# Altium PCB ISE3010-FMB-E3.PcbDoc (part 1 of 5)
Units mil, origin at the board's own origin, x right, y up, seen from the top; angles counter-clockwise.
Board outline 7874.02 x 2362.2 mil, 4 copper layers (Top Layer, MidLayer1, MidLayer2, Bottom Layer), stack 55.6 mil thick; 507 components, 331 nets, 1707 pads, 610 vias.
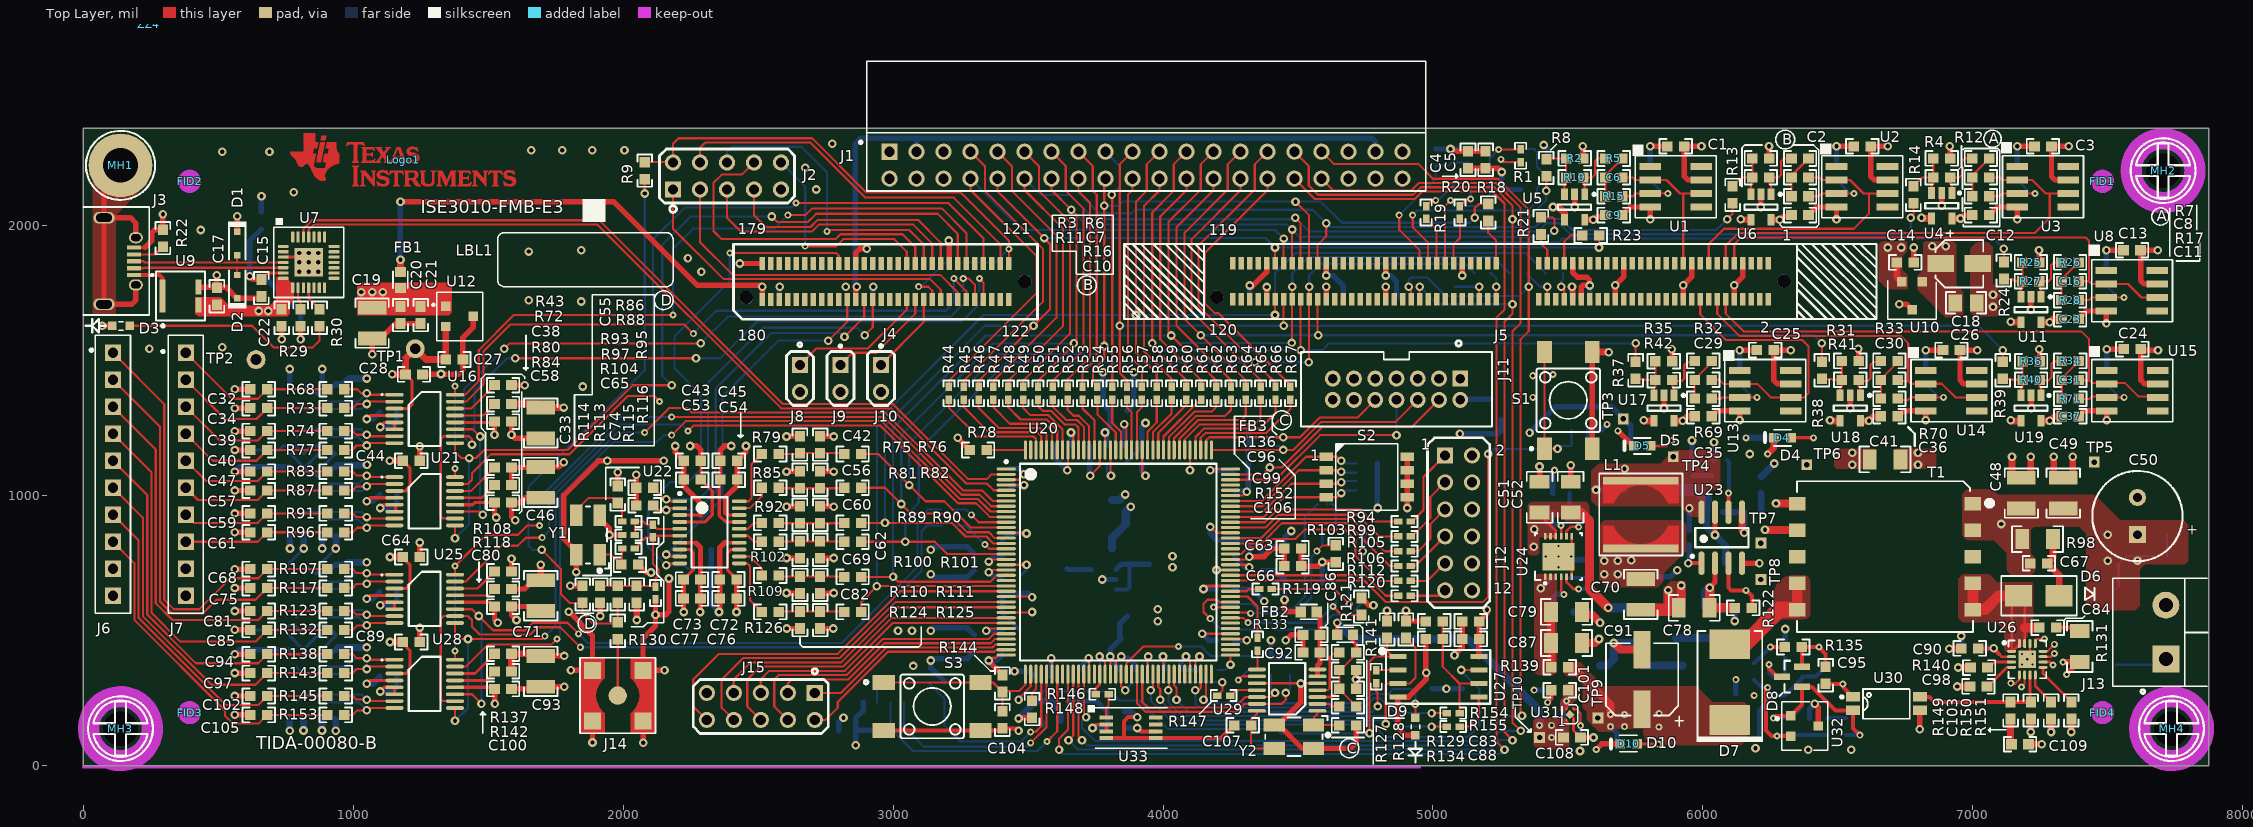
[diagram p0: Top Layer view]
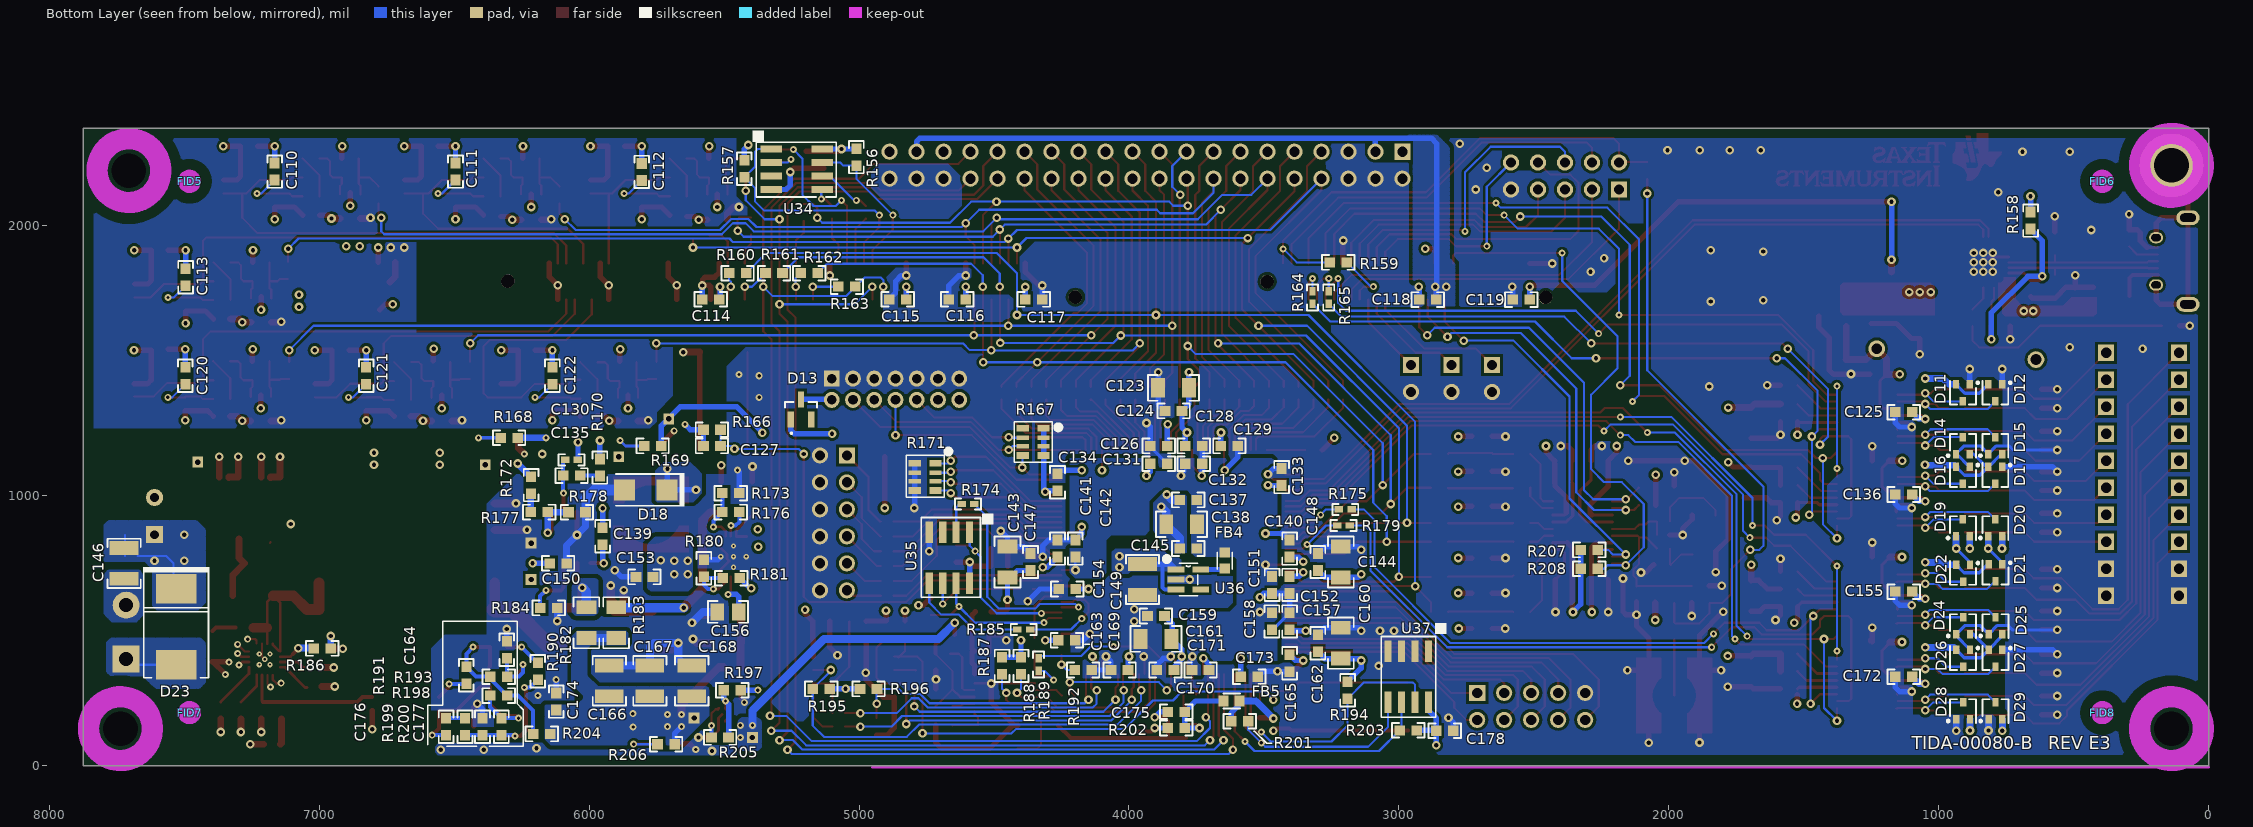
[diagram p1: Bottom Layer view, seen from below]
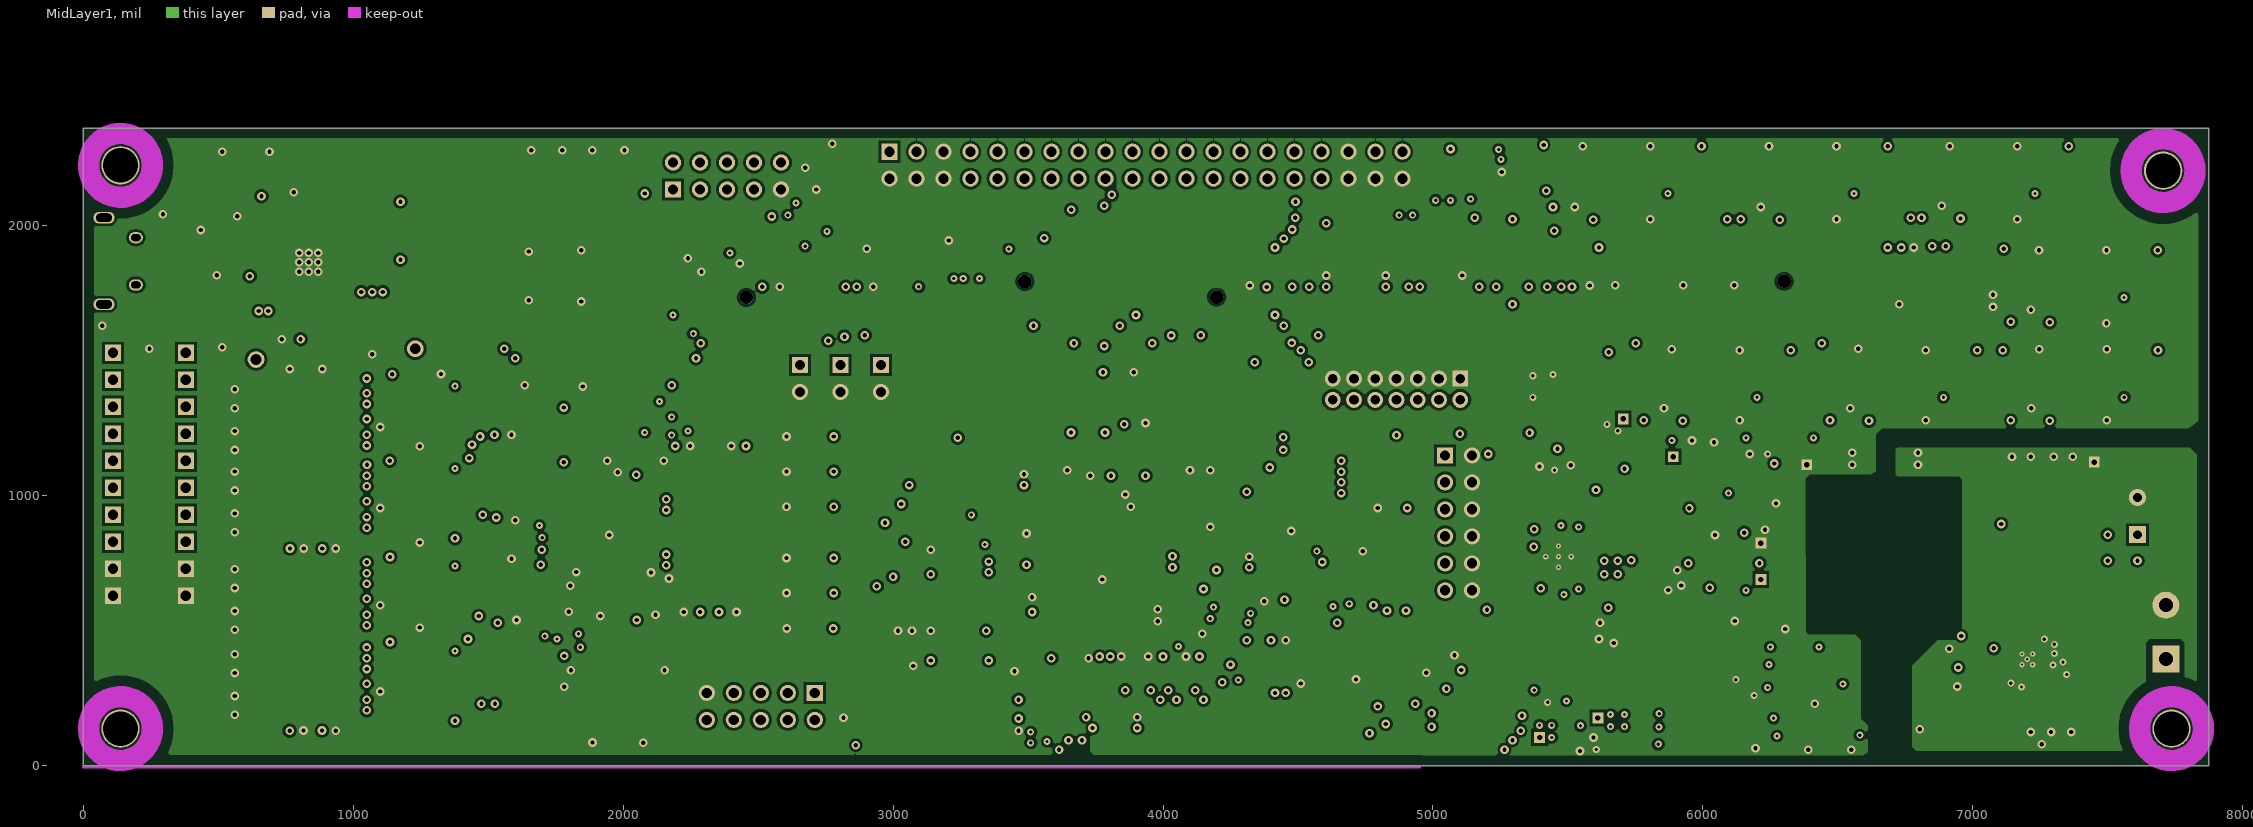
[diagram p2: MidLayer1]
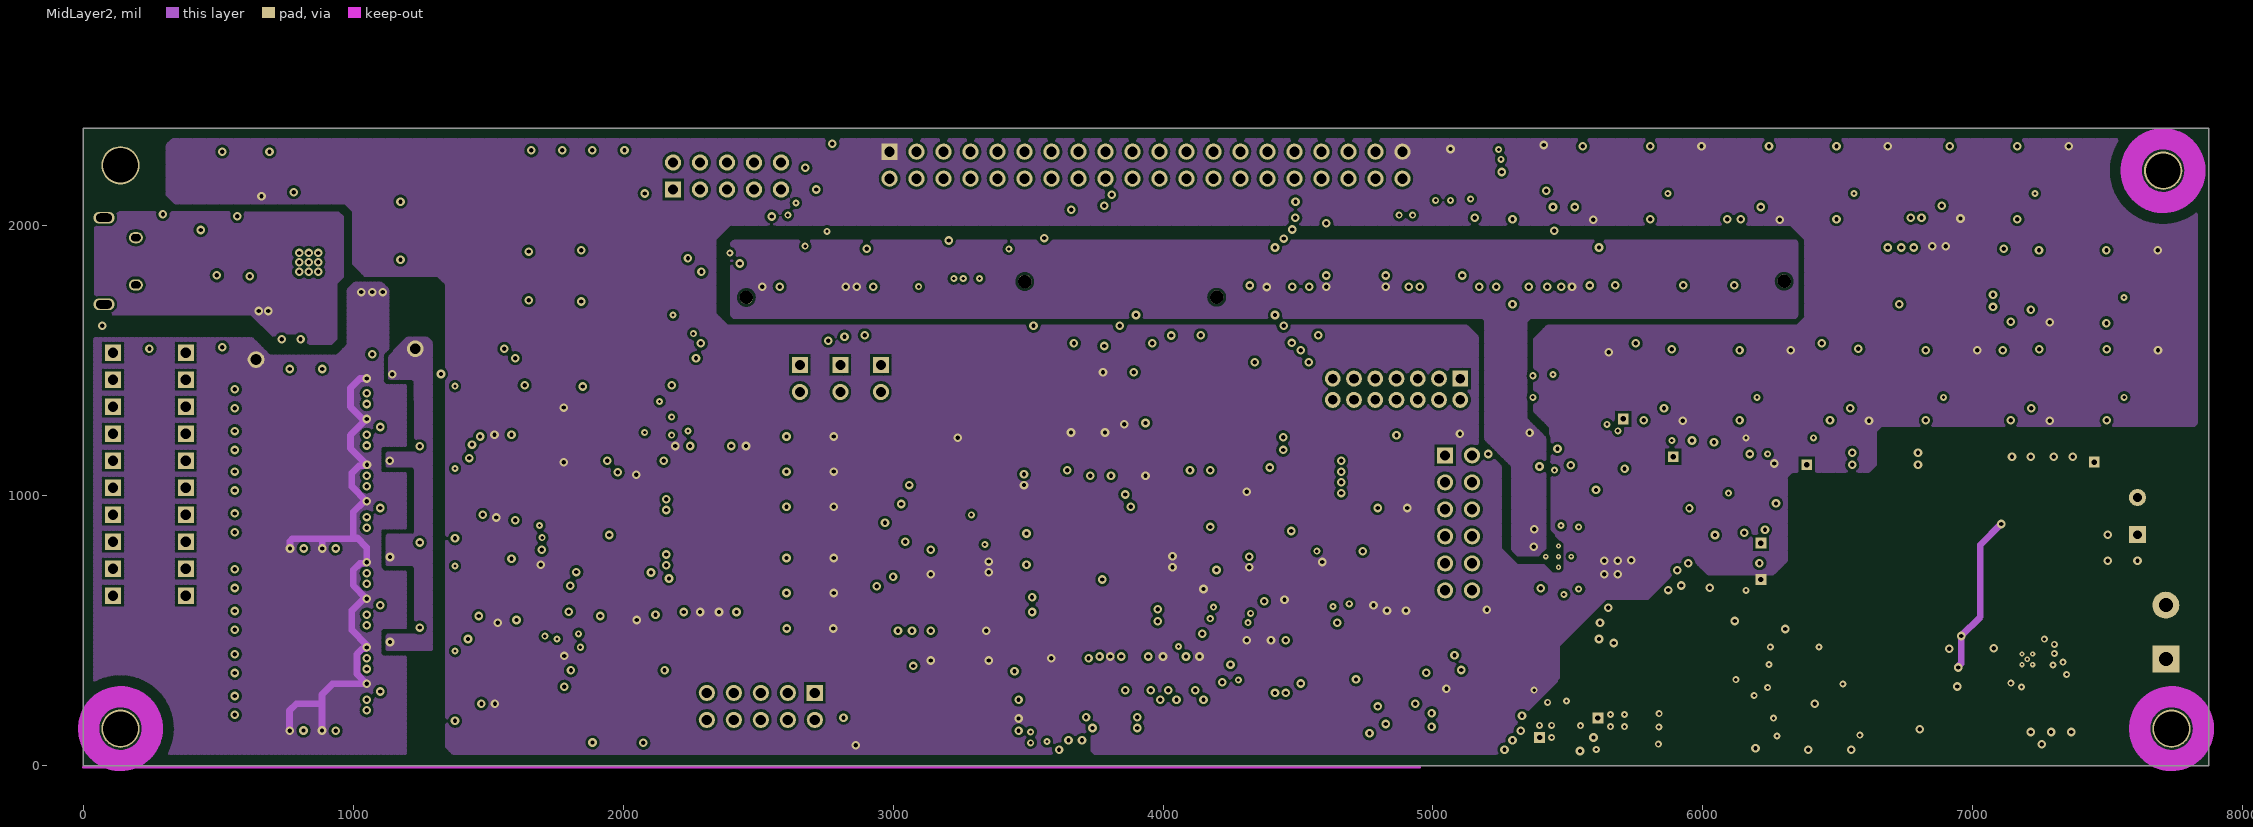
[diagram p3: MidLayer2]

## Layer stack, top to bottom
Top Layer: signal copper 1.4
Dielectric: core 16.6, FR-4, Dk 4.8
MidLayer1: signal copper 1.4
Dielectric: prepreg 16.8, FR-4, Dk 4.8
MidLayer2: signal copper 1.4
Dielectric: core 16.6, FR-4, Dk 4.8
Bottom Layer: signal copper 1.4

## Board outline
0,0 7874.02,0 7874.02,2362.2 0,2362.2

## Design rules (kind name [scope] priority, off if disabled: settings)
AcuteAngle [All] p1 off: minimum=4.50000000000000E+0001 checktracksonly=FALSE
AssemblyTestPointUsage [All] p1 off: valid=2
AssemblyTestpoint [All] p1 off: testpointundercomponent=TRUE minsize=40 maxsize=100 preferedsize=60 minholesize=0 maxholesize=40 preferedholesize=32 testpointgrid=1 usegrid=TRUE gridtolerance=0.01 allowsidetop=TRUE allowsidebottom=TRUE
Clearance "via to via" [IsVia vs IsVia] p1: gap=7.8
Clearance "Via to SMT Pin" [IsVia vs IsSMTPin] p2: gap=7.8
Clearance Clearance_Polygon [InPolygon vs InPolygon] p3: gap=15
Clearance Clearance_BoardEdge_Poly [OnCopper and InPoly vs IsKeepOut] p4: gap=40
Clearance Clearance_Poly [InPolygon] p5: gap=10
Clearance [All] p6: gap=7.5
ComponentClearance ComponentClearance_Logo [InComponentClass('Logo')] p1 off: gap=50 collisioncheckmode=3 verticalgap=10 showdistances=FALSE
ComponentClearance ComponentClearance_ScrewToNut [(HasFootprint('NY PMS 440 0025 PH')) vs (HasFootprint('Keystone_1902C'))] p2 off: gap=5 collisioncheckmode=3 verticalgap=10 showdistances=FALSE
ComponentClearance ComponentClearance_MountingHoles [InComponentClass('Mounting Holes')] p3 off: gap=250 collisioncheckmode=3 verticalgap=100000 showdistances=FALSE
ComponentClearance ComponentClearance_SmallPassives [HasFootprint('0201*') or HasFootprint('0402*') or HasFootprint('0508') or HasFootprint('0603*') or HasFootprint('0612') or HasFootprint('0805*') or HasFootprint('0815*') or HasFootprint('0830*') or HasFootprint('1206*') or HasFootprint('1210*') or HasFootprint('1808*') or HasFootprint('1812*') or HasFootprint('1825*') or HasFootprint('2010*') or HasFootprint('2220*') or HasFootprint('2225*') or HasFootprint('2512*') or HasFootprint('2728*') or HasFootprint('3518*') vs HasFootprint('0201*') or HasFootprint('0402*') or HasFootprint('0508') or HasFootprint('0603*') or HasFootprint('0612') or HasFootprint('0805*') or HasFootprint('0815*') or HasFootprint('0830*') or HasFootprint('1206*') or HasFootprint('1210*') or HasFootprint('1808*') or HasFootprint('1812*') or HasFootprint('1825*') or HasFootprint('2010*') or HasFootprint('2220*') or HasFootprint('2225*') or HasFootprint('2512*') or HasFootprint('2728*') or HasFootprint('3518*')] p4 off: gap=20 collisioncheckmode=3 verticalgap=10 showdistances=FALSE
ComponentClearance ComponentClearance_THtoSMT [IsThruComponent vs IsSMTComponent] p5 off: gap=100 collisioncheckmode=3 verticalgap=30 showdistances=FALSE
ComponentClearance ComponentClearance_THtoTH [IsThruComponent vs IsThruComponent] p6 off: gap=118.11 collisioncheckmode=3 verticalgap=30 showdistances=FALSE
ComponentClearance [All] p7 off: gap=40 collisioncheckmode=3 verticalgap=10 showdistances=FALSE
DiffPairsRouting DiffPair_RS232DiffPairsRouting [InDifferentialPair ('RS232')] p1 off: maxlimit=8 minlimit=8 mostfreqgap=8 maxuncoupledlength=500
DiffPairsRouting [All] p2 off: maxlimit=8 minlimit=8 mostfreqgap=8 maxuncoupledlength=1000
FabricationTestPointUsage TestPointUsage [All] p1 off: valid=2 allowmultiple=FALSE
FabricationTestpoint Testpoint [All] p1 off: side=3 testpointundercomponent=TRUE minsize=40 maxsize=100 preferedsize=60 minholesize=0 maxholesize=40 preferedholesize=32 testpointgrid=1 allowsidetop=TRUE allowsidebottom=TRUE usegrid=TRUE gridtolerance=0.01
FanoutControl Fanout_LCC [IsLCC] p1 off: bgadir=Out bgaviamode=Centered fanoutstyle=Auto fanoutdirection=Alternating viagrid=1 // Fanout_LCC (Default Rule)
FanoutControl Fanout_BGA [IsBGA] p2 off: bgadir=Out bgaviamode=Centered fanoutstyle=Auto fanoutdirection=Alternating viagrid=1 // Fanout_BGA (Default Rule)
FanoutControl Fanout_SOIC [IsSOIC] p3 off: bgadir=Out bgaviamode=Centered fanoutstyle=Auto fanoutdirection=Alternating viagrid=1 // Fanout_SOIC (Default Rule)
FanoutControl Fanout_Default [All] p4 off: bgadir=Out bgaviamode=Centered fanoutstyle=Auto fanoutdirection=Alternating viagrid=1 // Fanout_Default (Default Rule)
FanoutControl Fanout_Small [(CompPinCount < 5)] p5 off: bgadir=Out bgaviamode=Centered fanoutstyle=Auto fanoutdirection=OutThenIn viagrid=1 // Fanout_Small (Default Rule)
Height [All] p1 off: minheight=0 maxheight=1000 prefheight=500
HoleSize [All] p1: absolutevalues=TRUE maxlimit=251 minlimit=8 maxpercent=80.000 minpercent=20.000
MatchedLengths DiffPair_RS232MatchedLengths [InDifferentialPair ('RS232')] p1: tolerance=1000 checknetsindiffpair=TRUE checkdiffpairvsdiffpair=TRUE checkothers=TRUE
MinimumAnnularRing MinimumAnnularRing_ThermalPadVias [IsVia and InAnyComponent] p1 off: minimumring=5.91
MinimumAnnularRing [All] p2 off: minimumring=9
MinimumSolderMaskSliver MinimumSolderMaskSliver_Logo [InComponentClass('Logo') vs InComponentClass('Logo')] p1 off: minsoldermaskwidth=0.7
MinimumSolderMaskSliver [All] p2 off: minsoldermaskwidth=3.94
NetAntennae [All] p1 off: netantennaetolerance=0
PasteMaskExpansion [All] p1 off: expansion=0
PlaneClearance [All] p1: clearance=15
PlaneConnect [All] p1: planeconnectstyle=Direct reliefexpansion=10 reliefentries=4 reliefconductorwidth=10 reliefairgap=10
PolygonConnect [All] p1: connectstyle=Direct reliefconductorwidth=10 reliefentries=4 polygonreliefangle="90 Angle"
RoutingCorners [All] p1 off: cornerstyle=45-Degree minsetback=100 maxsetback=100
RoutingLayers [All] p1 off: top layer_v5=TRUE mid layer 1_v5=TRUE mid layer 2_v5=TRUE bottom layer_v5=TRUE
RoutingPriority [All] p1 off: routingpriority=0
RoutingTopology [All] p1 off: topology=Shortest
RoutingVias ThermalPadVias [IsVia and InAnyComponent] p1 off: holewidth=16 width=32 viastyle="Through Hole" minholewidth=16 minwidth=32 maxholewidth=16 maxwidth=32
RoutingVias [All] p2: holewidth=12 width=26 viastyle="Through Hole" minholewidth=8 minwidth=20 maxholewidth=16 maxwidth=32
SMDToCorner [All] p1 off: distance=30000
SilkToSilkClearance [All] p1 off: silktosilkclearance=0
SilkscreenOverComponentPads [All] p1 off: minsilkscreentomaskgap=0
SolderMaskExpansion [All] p1 off: expansion=1.97
Width DiffPair_RS232Width [InDifferentialPair('RS232')] p1: maxlimit=100 minlimit=8 preferedwidth=8
Width [All] p2: maxlimit=100 minlimit=8 preferedwidth=20 checkconnectedcopper=TRUE
4 further rules are at their usual default settings.

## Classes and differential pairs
component class "FPGA Power": C104 C123 C124 C126 C128 C129 C131 C132 C133 C134 C137 C138 C140 C141 C142 C143 C144 C147 C148 C151 C152 C154 C157 C158 C159 C160 C161 C162 C163 C165 C169 C170 C171 C173 D9 D13 J11 R144 R167 R175 R179 R192 R196 S3
component class DAC: C28 C32 C33 C34 C38 C39 C40 C44 C46 C47 C57 C58 C59 C61 C64 C68 C71 C75 C80 C81 C85 C89 C93 C94 C97 C100 C102 C105 C125 C136 C155 C172 D11 D12 D14 D15 D16 D17 D19 D20 D21 D22 D24 D25 D26 D27 D28 D29 J6 J7 J12 J15 R43 R68 R72 R73 R74 R77 R80 R83 R84 R87 R91 R96 R107 R108 R117 R118 R123 R132 R137 R138 R142 R143 R145 R153 U16 U21 U25 U28
component class "Mounting Holes": MH1 MH2 MH3 MH4
component class Logo: Logo1
component class Hardware: FID1 FID2 FID3 FID4 FID5 FID6 FID7 FID8 LBL1 Logo1 MH1 MH2 MH3 MH4 ZZ1 ZZ2 ZZ3 ZZ4
component class FiducialMark: FID1 FID2 FID3 FID4 FID5 FID6 FID7 FID8
component class AssemblyNote: ZZ1 ZZ2 ZZ3 ZZ4
component class Label: LBL1
component class "FPGA CLOCK_USB": C15 C17 C22 C42 C43 C45 C53 C54 C55 C56 C60 C62 C63 C65 C66 C69 C72 C73 C74 C76 C77 C82 C83 C86 C88 C92 C96 C99 C106 C107 C127 C175 C178 D1 D2 D3 FB2 FB3 FB5 J3 J14 R9 R22 R29 R30 R44 R45 R46 R47 R48 R49 R50 R51 R52 R53 R54 R55 R56 R57 R58 R59 R60 R61 R62 R63 R64 R65 R66 R67 R75 R76 R78 R79 R81 R82 R85 R86 R88 R89 R90 R92 R93 R94 R95 R97 R99 R100 R101 R102 R103 R104 R105 R106 R109 R110 R111 R112 R113 R114 R115 R116 R119 R120 R121 R124 R125 R126 R127 R128 R129 R130 R133 R134 R136 R141 R146 R147 R148 R152 R154 R155 R158 R166 R171 R174 R185 R187 R188 R189 R194 R195 R201 R202 R203 R207 R208 S1 S2 U7 U9 U20 U22 U27 U29 U33 U35 U37 U59 Y1 Y2
component class "SDM OP Filtering": C1 C2 C3 C6 C7 C8 C9 C10 C11 C12 C13 C14 C16 C18 C19 C20 C21 C23 C24 C25 C26 C27 C29 C30 C31 C35 C36 C37 C110 C111 C112 C113 C120 C121 C122 FB1 R2 R3 R4 R5 R6 R7 R8 R10 R11 R12 R13 R14 R15 R16 R17 R24 R25 R26 R27 R28 R31 R32 R33 R34 R35 R36 R37 R38 R39 R40 R41 R42 R69 R70 R71 TP1 TP2 U1 U2 U3 U4 U5 U6 U8 U10 U11 U12 U13 U14 U15 U17 U18 U19
component class "Control card connector": C4 C5 C114 C115 C116 C117 C118 C119 J1 J2 J4 J5 J8 J9 J10 R1 R18 R19 R20 R21 R23 R156 R157 R159 R160 R161 R162 R163 R164 R165 U34
component class "Power Supply": C41 C48 C49 C50 C51 C52 C67 C70 C78 C79 C84 C87 C90 C91 C95 C98 C101 C103 C108 C109 C130 C135 C139 C145 C146 C149 C150 C153 C156 C164 C166 C167 C168 C174 C176 C177 D4 D5 D6 D7 D8 D10 D18 D23 FB4 J13 L1 R98 R122 R131 R135 R139 R140 R149 R150 R151 R168 R169 R170 R172 R173 R176 R177 R178 R180 R181 R182 R183 R184 R186 R190 R191 R193 R197 R198 R199 R200 R204 R205 R206 T1 TP3 TP4 TP5 TP6 TP7 TP8 TP9 TP10 U23 U24 U26 U30 U31 U32 U36

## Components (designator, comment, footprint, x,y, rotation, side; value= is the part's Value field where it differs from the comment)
C1 "" 0603 5900,2295 r0 top (schematic designator C130)
C2 "" 0603 6590,2295 r0 top (schematic designator C144)
C3 "" 0603 7260,2295 r0 top (schematic designator C152)
C4 "0603YC104JAT2A" 0603 5130,2245 r270 top (schematic designator C114)
C5 "C1608X5R1C105K" 0603 5195,2245 r270 top (schematic designator C115)
C6 "" 0603 5670,2180 r0 top (schematic designator C132)
C7 "" 0603 6360,2180 r0 top (schematic designator C147)
C8 "" 0603 7030,2180 r0 top (schematic designator C154)
C9 "" 0603 5670,2040 r180 top (schematic designator C129)
C10 "" 0603 6360,2040 r180 top (schematic designator C143)
C11 "" 0603 7030,2040 r180 top (schematic designator C151)
C12 "EEE-FC1C100R" SM_RADIAL_B 6950,1860 r0 top (schematic designator C141)
C13 "" 0603 7590,1910 r0 top (schematic designator C146)
C14 "06033C104JAT2A" 0603 6750,1865 r0 top (schematic designator C140)
C15 "GRM188R70J224KA88D" 0603 660,1770 r270 top (schematic designator C63)
C16 "" 0603 7360.31,1795 r0 top (schematic designator C148)
C17 "GRM188R70J224KA88D" 0603 495,1740 r90 top (schematic designator C58)
C18 "0805YC474KAT2A" 0805_HV 6975,1715 r0 top (schematic designator C142)
C19 "" 1210 1070,1640 r270 top (schematic designator C136)
C20 "" 0603 1175,1670 r270 top (schematic designator C138)
C21 "" 0603 1250,1670 r90 top (schematic designator C137)
C22 "C0603C475K9PACTU" 0603 735,1660 r270 top (schematic designator C59)
C23 "" 0603 7360.31,1655 r180 top (schematic designator C145)
C24 "" 0603 7591,1543.54 r0 top (schematic designator C150)
C25 "" 0603 6231,1540 r0 top (schematic designator C134)
C26 "" 0603 6921,1540 r0 top (schematic designator C128)
C27 "" 0603 1375,1505 r0 top (schematic designator C139)
C28 "" 0603 1225,1450 r180 top (schematic designator C9)
C29 "" 0603 6001,1430 r0 top (schematic designator C135)
C30 "" 0603 6691,1430 r0 top (schematic designator C131)
C31 "" 0603 7361,1430 r0 top (schematic designator C153)
C32 "" 0603 650,1395 r0 top (schematic designator C7)
C33 "" 1210 1695,1270 r270 top (schematic designator C105)
C34 "" 0603 650,1325 r0 top (schematic designator C8)
C35 "" 0603 6001,1295 r180 top (schematic designator C133)
C36 "" 0603 6691,1295 r180 top (schematic designator C127)
C37 "" 0603 7361,1295 r180 top (schematic designator C149)
C38 "" 0603 1555,1275 r180 top (schematic designator C13)
C39 "" 0603 650,1240 r0 top (schematic designator C11)
C40 "" 0603 650,1170 r0 top (schematic designator C12)
C41 "" 1206 6675,1135 r180 top (schematic designator C111)
C42 "06031C103KAT2A" 0603 2850,1155 r180 top (schematic designator C39)
C43 "06033C104JAT2A" 0603 2256.5,1130 r0 top (schematic designator C47)
C44 "" 0603 1215,1130 r180 top (schematic designator C17)
C45 "06033C104JAT2A" 0603 2391.5,1130 r180 top (schematic designator C51)
C46 "" 1210 1695,1050 r270 top (schematic designator C22)
C47 "" 0603 650,1090 r0 top (schematic designator C15)
C48 "GRM32ER71H106KA12L" 1210 7180,1010 r90 top (schematic designator C109)
C49 "GRM32ER71H106KA12L" 1210 7335,1010 r90 top (schematic designator C108)
C50 "UHE1H101MPD" HE_800x1150 7610,925 r90 top (schematic designator C112)
C51 "GRM31CR71C106KAC7L" 1206 5395,995 r90 top (schematic designator C180)
C52 "GRM31CR71C106KAC7L" 1206 5510,995 r90 top (schematic designator C181)
C53 "06033C104JAT2A" 0603 2256.5,1060 r0 top (schematic designator C46)
C54 "06033C104JAT2A" 0603 2391.5,1060 r180 top (schematic designator C50)
C55 "06035A270JAT2A" 0603 1980,1005 r90 top (schematic designator C183)
C56 "06031C103KAT2A" 0603 2850,1030 r180 top (schematic designator C40)
C57 "" 0603 650,1020 r0 top (schematic designator C16)
C58 "" 0603 1555,975 r180 top (schematic designator C21)
C59 "" 0603 650,935 r0 top (schematic designator C19)
C60 "06031C103KAT2A" 0603 2850,900 r180 top (schematic designator C41)
C61 "" 0603 650,865 r0 top (schematic designator C20)
C62 "06031C103KAT2A" 0603 2850,830 r180 top (schematic designator C42)
C63 "C1608X5R1C105K" 0603 4480,805 r180 top (schematic designator C117)
C64 "" 0603 1215,773.54 r180 top (schematic designator C25)
C65 "06035A270JAT2A" 0603 2025,745 r0 top (schematic designator C182)
C66 "0603YC104JAT2A" 0603 4480,740 r180 top (schematic designator C116)
C67 "C0603C104K5RACTU" 0603 7245,750 r0 top (schematic designator C123)
C68 "" 0603 650,728.54 r0 top (schematic designator C23)
C69 "06031C103KAT2A" 0603 2850,700 r180 top (schematic designator C43)
C70 "C3225X5R1A226M" 1210 5770,635 r270 top (schematic designator C160)
C71 "" 1210 1695,630 r270 top (schematic designator C30)
C72 "06033C104JAT2A" 0603 2390,690 r0 top (schematic designator C52)
C73 "06033C104JAT2A" 0603 2255,690 r180 top (schematic designator C48)
C74 "06031C103KAT2A" 0603 1980,635 r270 top (schematic designator C45)
C75 "" 0603 650,658.54 r0 top (schematic designator C24)
C76 "06033C104JAT2A" 0603 2390,620 r0 top (schematic designator C53)
C77 "06033C104JAT2A" 0603 2255,620 r180 top (schematic designator C49)
C78 "GMK316AB7106KL" 1206 5967.91,585 r180 top (schematic designator C155)
C79 "12063C105KAT2A" 1206 5495,570 r0 top (schematic designator C178)
C80 "" 0603 1555,590 r180 top (schematic designator C29)
C81 "" 0603 650,573.54 r0 top (schematic designator C27)
C82 "06031C103KAT2A" 0603 2850,570 r180 top (schematic designator C44)
C83 "C0603C475K9PACTU" 0603 5140,535 r0 top (schematic designator C56)
C84 "06035A331JAT2A" 0603 7278,512 r0 top (schematic designator C125)
C85 "" 0603 650,503.54 r0 top (schematic designator C28)
C86 "C0603C475K9PACTU" 0603 4550,485 r0 top (schematic designator C57)
C87 "GRM31CR71C106KAC7L" 1206 5495,455 r0 top (schematic designator C175)
C88 "GRM188R70J224KA88D" 0603 5140,470 r0 top (schematic designator C55)
C89 "" 0603 1215,458.54 r180 top (schematic designator C33)
C90 "C0603C104K5RACTU" 0603 6989,435 r180 top (schematic designator C110)
C91 "UUD1C151MCL1GS" SM_RADIAL_6.3BMM 5775,320 r90 top (schematic designator C119)
C92 "GRM188R70J224KA88D" 0603 4550,420 r0 top (schematic designator C62)
C93 "" 1210 1695,350 r270 top (schematic designator C38)
C94 "" 0603 650,413.54 r0 top (schematic designator C31)
C95 "GRM188R71H393KA61D" 0603 6455,335 r270 top (schematic designator C122)
C96 "C0603C475K9PACTU" 0603 4685,355 r180 top (schematic designator C60)
C97 "" 0603 650,343.54 r0 top (schematic designator C32)
C98 "06035C104KAT2A" 0603 7021,294 r180 top (schematic designator C121)
C99 "GRM188R70J224KA88D" 0603 4685,285.32 r180 top (schematic designator C61)
C100 "" 0603 1555,285 r180 top (schematic designator C37)
C101 "GRM188R71A105KA61D" 0603 5470,280 r180 top (schematic designator C165)
C102 "" 0603 650,258.54 r0 top (schematic designator C35)
C103 "C1608C0G1H101J" 0603 7215,205 r270 top (schematic designator C107)
C104 "C0603C475K9PACTU" 0603 3405,170 r90 top (schematic designator C100)
C105 "" 0603 650,188.54 r0 top (schematic designator C36)
C106 "06035A270JAT2A" 0603 4685,150 r0 top (schematic designator C64)
C107 "06035A270JAT2A" 0603 4295,150 r180 top (schematic designator C65)
C108 "GRM188R71A105KA61D" 0603 5515,105 r0 top (schematic designator C166)
C109 "C0603C104K5RACTU" 0603 7175,80 r0 top (schematic designator C126)
C110 "" 0603 7165,2201.5 r270 bottom (schematic designator C187)
C111 "" 0603 6495,2201.5 r270 bottom (schematic designator C190)
C112 "" 0603 5805,2200 r270 bottom (schematic designator C185)
C113 "" 0603 7495,1810 r270 bottom (schematic designator C186)
C114 "" 0603 5549.21,1728.07 r180 bottom (schematic designator C4)
C115 "" 0603 4856.3,1728.07 r180 bottom (schematic designator C1)
C116 "" 0603 4635.83,1728.07 r180 bottom (schematic designator C2)
C117 "" 0603 4352.36,1728.07 r0 bottom (schematic designator C5)
C118 "" 0603 2893.44,1727.07 r180 bottom (schematic designator C3)
C119 "" 0603 2546.98,1727.07 r180 bottom (schematic designator C6)
C120 "" 0603 7496,1445 r270 bottom (schematic designator C191)
C121 "" 0603 6826,1445 r270 bottom (schematic designator C188)
C122 "" 0603 6136,1445 r270 bottom (schematic designator C189)
C123 "GRM31CR60J107ME39L" 1206 3835,1400 r0 bottom (schematic designator C67)
C124 "C0603C475K9PACTU" 0603 3835,1315 r0 bottom (schematic designator C68)
C125 "" 0603 1130,1310 r180 bottom (schematic designator C10)
C126 "GRM188R70J224KA88D" 0603 3890,1185 r180 bottom (schematic designator C70)
C127 "C0603C475K9PACTU" 0603 5545,1185 r180 bottom (schematic designator C54)
C128 "GRM188R70J224KA88D" 0603 3760,1185 r0 bottom (schematic designator C72)
C129 "GRM188R70J224KA88D" 0603 3627.95,1185 r0 bottom (schematic designator C69)
C130 "GRM1555C1E470JA01D" 0402 6065,1133.5 r180 bottom (schematic designator C158)
C131 "GRM188R70J224KA88D" 0603 3890,1119.02 r0 bottom (schematic designator C71)
C132 "GRM188R70J224KA88D" 0603 3760,1119.02 r0 bottom (schematic designator C84)
C133 "GRM188R70J224KA88D" 0603 3434.65,1069.84 r270 bottom (schematic designator C97)
C134 "GRM188R70J224KA88D" 0603 4265,1050 r270 bottom (schematic designator C83)
C135 "GRM1885C1E681JA01D" 0603 6065,1075 r180 bottom (schematic designator C157)
C136 "" 0603 1130,1005 r180 bottom (schematic designator C18)
C137 "C0603C475K9PACTU" 0603 3780,985 r0 bottom (schematic designator C89)
C138 "GRM31CR60J107ME39L" 1206 3805,895 r0 bottom (schematic designator C90)
C139 "0603YC104JAT2A" 0603 5950,850 r270 bottom (schematic designator C159)
C140 "GRM188R70J224KA88D" 0603 3405,805 r270 bottom (schematic designator C98)
C141 "GRM188R70J224KA88D" 0603 4265,805 r270 bottom (schematic designator C76)
C142 "GRM188R70J224KA88D" 0603 4198.82,805 r270 bottom (schematic designator C88)
C143 "GRM31CR60J107ME39L" 1206 4450,755 r90 bottom (schematic designator C79)
C144 "GRM31CR60J107ME39L" 1206 3215,755 r90 bottom (schematic designator C95)
C145 "C0603C475K9PACTU" 0603 3780,805 r0 bottom (schematic designator C102)
C146 "" 1210 7723,750 r270 bottom (schematic designator C120)
C147 "C0603C475K9PACTU" 0603 4365,755 r90 bottom (schematic designator C80)
C148 "C0603C475K9PACTU" 0603 3300,755 r90 bottom (schematic designator C96)
C149 "" 1210 3950,690 r270 bottom (schematic designator C101)
C150 "GRM188R71C153KA01D" 0603 6115,750 r180 bottom (schematic designator C156)
C151 "GRM188R70J224KA88D" 0603 3470,670 r90 bottom (schematic designator C85)
C152 "GRM188R70J224KA88D" 0603 3405,670 r90 bottom (schematic designator C73)
C153 "C0603X104K8RACTU" 0603 5795,700 r0 bottom (schematic designator C192)
C154 "GRM188R70J224KA88D" 0603 4228.35,655 r180 bottom (schematic designator C81)
C155 "" 0603 1130,645 r180 bottom (schematic designator C26)
C156 "08055C103KAT2A" 0805_HV 5485,570 r0 bottom (schematic designator C179)
C157 "GRM188R70J224KA88D" 0603 3405,535 r270 bottom (schematic designator C99)
C158 "GRM188R70J224KA88D" 0603 3470.47,535 r90 bottom (schematic designator C86)
C159 "C0603C475K9PACTU" 0603 3900,555 r0 bottom (schematic designator C92)
C160 "GRM31CR60J107ME39L" 1206 3215,454.2 r90 bottom (schematic designator C78)
C161 "GRM31CR60J107ME39L" 1206 3900,470 r0 bottom (schematic designator C91)
C162 "C0603C475K9PACTU" 0603 3300,454.2 r90 bottom (schematic designator C77)
C163 "GRM188R70J224KA88D" 0603 4230,465 r0 bottom (schematic designator C82)
C164 "C0603C105K4PACTU" 0603 6305,430 r90 bottom (schematic designator C124)
C165 "GRM188R70J224KA88D" 0603 3405,380 r90 bottom (schematic designator C74)
C166 "GRM32ER61A476KE20L" 1210 5925,315 r90 bottom (schematic designator C104)
C167 "GRM32ER61A476KE20L" 1210 5775,315 r90 bottom (schematic designator C118)
C168 "GRM32ER61A476KE20L" 1210 5620,315 r90 bottom (schematic designator C193)
C169 "GRM188R70J224KA88D" 0603 4035,355 r180 bottom (schematic designator C94)
C170 "GRM188R70J224KA88D" 0603 3865,355 r180 bottom (schematic designator C75)
C171 "GRM188R70J224KA88D" 0603 3735,355 r0 bottom (schematic designator C87)
C172 "" 0603 1130,330 r180 bottom (schematic designator C34)
C173 "GRM188R70J224KA88D" 0603 3555,330 r0 bottom (schematic designator C93)
C174 "C0603X104K8RACTU" 0603 6122,238 r90 bottom (schematic designator C103)
C175 "GRM188R70J224KA88D" 0603 3825,200 r180 bottom (schematic designator C66)
C176 "C1608C0G1H101J" 0603 6530,145 r270 bottom (schematic designator C14)
C177 "C0603C104K5RACTU" 0603 6325,145 r270 bottom (schematic designator C106)
C178 "0603YC104JAT2A" 0603 2830,130 r180 bottom (schematic designator C184)
D1 "PESD1LIN,115" sod-323 570,1935 r270 top (schematic designator D18)
D2 "PESD1LIN,115" sod-323 570,1775 r90 top (schematic designator D19)
D3 "" LED0603AA 140,1630 r0 top (schematic designator D17)
D4 "LG L29K-G2J1-24-Z" LED_0603 6295,1215 r180 top (schematic designator D27)
D5 "LG L29K-G2J1-24-Z" LED_0603 5775,1185 r180 top (schematic designator D28)
D6 "D-MURA105T3" 403D 7245,630 r180 top (schematic designator D23)
D7 "MBRS340T3G" SMC 6100,310 r90 top (schematic designator D22)
D8 "BAT54S-7-F" SOT-23#1 6330,330 r180 top (schematic designator D24)
D9 "" LED0603AA 4935,145 r90 top (schematic designator D21)
D10 "LG L29K-G2J1-24-Z" LED_0603 5725,81 r180 top (schematic designator D29)
D11 "" SOT-323 910.71,1381.57 r270 bottom (schematic designator D1)
D12 "" SOT-323 790.71,1381.57 r270 bottom (schematic designator D3)
D13 "BAS16-7-F" SOT-23#1 5215,1320 r90 bottom (schematic designator D20)
D14 "" SOT-323 910.71,1186.57 r90 bottom (schematic designator D4)
D15 "" SOT-323 790.71,1186.57 r90 bottom (schematic designator D2)
D16 "" SOT-323 910.71,1076.57 r270 bottom (schematic designator D5)
D17 "" SOT-323 790.71,1076.57 r270 bottom (schematic designator D6)
D18 "B220A-13-F" SMA 5790,1022 r0 bottom (schematic designator D26)
D19 "" SOT-323 910.71,881.57 r90 bottom (schematic designator D9)
D20 "" SOT-323 790.71,881.57 r90 bottom (schematic designator D7)
D21 "" SOT-323 790,715 r270 bottom (schematic designator D11)
D22 "" SOT-323 910,713.54 r270 bottom (schematic designator D8)
D23 "MBRS4201T3G" SMC 7530,515 r270 bottom (schematic designator D25)
D24 "" SOT-323 910,518.54 r90 bottom (schematic designator D12)
D25 "" SOT-323 790,518.54 r90 bottom (schematic designator D10)
D26 "" SOT-323 910,398.54 r270 bottom (schematic designator D13)
D27 "" SOT-323 790,398.54 r270 bottom (schematic designator D14)
D28 "" SOT-323 910,203.54 r90 bottom (schematic designator D16)
D29 "" SOT-323 790,203.54 r90 bottom (schematic designator D15)
FB1 "" FB0603 1175,1800 r270 top (schematic designator FB4)
FB2 "" FB0603 4540,570 r0 top (schematic designator FB1)
FB3 "" FB0603 4675,485.32 r0 top (schematic designator FB2)
FB4 "" FB0603 3645,760 r90 bottom (schematic designator FB5)
FB5 "" FB0603 3620,240 r0 bottom (schematic designator FB3)
FID1 "" Fiducial10-20 7480.31,2165.35 r0 top locked (schematic designator FID2)
FID2 "" Fiducial10-20 393.7,2165.35 r0 top locked (schematic designator FID1)
FID3 "" Fiducial10-20 393.7,196.85 r90 top locked (schematic designator FID4)
FID4 "" Fiducial10-20 7480.31,196.85 r0 top (schematic designator FID3)
FID5 "" Fiducial10-20 7480.31,2165.35 r180 bottom (schematic designator FID7)
FID6 "" Fiducial10-20 393.7,2165.35 r180 bottom
FID7 "" Fiducial10-20 7480.31,196.85 r180 bottom (schematic designator FID8)
FID8 "" Fiducial10-20 393.7,196.85 r180 bottom (schematic designator FID5)
J1 "613040243121" CONN_613040243121 3937.01,2225 r0 top locked (schematic designator J4)
J2 "HEADER_2X5" HEADER_2X5 2185,2135 r0 top (schematic designator J7)
J3 "CONN_USB_SD-47590-001" USB-SD-47590-001 80,1870 r0 top (schematic designator J13)
J4 "SPD08-060-RB-TR" HSEC8-130-01-L-DV-A 2972.18,1794 r0 top (schematic designator J6)
J5 "SPD08-120-L-RB" HSEC8-160-01-L-DV-A-L 5250,1795 r0 top
J6 "HEADER_1X10" HDR100_1X10 110,1530 r270 top (schematic designator J11)
J7 "HEADER_1X10" HDR100_1X10 380,1530 r270 top (schematic designator J9)
J8 "" HDR100_1X2 2655,1485 r270 top (schematic designator J3)
J9 "" HDR100_1X2 2805,1485 r270 top (schematic designator J2)
J10 "" HDR100_1X2 2955,1485 r270 top (schematic designator J1)
J11 "0878311420" CONN_0878311420 4865,1395 r180 top (schematic designator J14)
J12 "HEADER_2X6" HEADER_2X6 5045,1150 r270 top (schematic designator J10)
J13 "TBLK_15A_2X5.1MM" TB_2X5.1MM 7715,395 r90 top (schematic designator J15)
J14 "142-0711-201" 142-0711-201 1980,260 r180 top (schematic designator J12)
J15 "HEADER_2X5" HEADER_2X5 2710,270 r180 top (schematic designator J8)
L1 "MSS7341-332NLB" MSS7341 5770,930.49 r270 top (schematic designator L4)
LBL1 "" Label_650x200 1860,1875 r0 top
Logo1 "" TI_Stacked_SolderMask_Small 1185,2245 r0 top
MH1 "" MH3.2 137.8,2224.41 r0 top
MH2 "" MH3.2_NPTH 7705,2205 r0 top (schematic designator MH3)
MH3 "" MH3.2_NPTH 137.8,137.8 r0 top locked (schematic designator MH4)
MH4 "" MH3.2_NPTH 7736.22,137.8 r0 top locked (schematic designator MH2)
R1 "CRCW040222R0JNED" 0402 5325,2260 r90 top (schematic designator R203)
R2 "RC0603FR-07270KL" 0603 5525,2250 r0 top (schematic designator R146)
R3 "RC0603FR-07270KL" 0603 6215,2250 r0 top (schematic designator R160)
R4 "RC0603FR-07270KL" 0603 6885,2250 r0 top (schematic designator R171)
R5 "" 0603 5670,2250 r180 top (schematic designator R141)
R6 "" 0603 6360,2250 r180 top (schematic designator R154)
R7 "" 0603 7030,2250 r180 top (schematic designator R166)
R8 "CRCW06037K50FKEA" 0603 5420,2215 r270 top (schematic designator R144)
R9 "CRCW06030000Z0EA" 0603 2080,2205 r90 top (schematic designator R75)
R10 "CRCW0603100KFKEA" 0603 5525,2180 r0 top (schematic designator R148)
R11 "CRCW0603100KFKEA" 0603 6215,2180 r0 top (schematic designator R162)
R12 "CRCW0603100KFKEA" 0603 6885,2180 r0 top (schematic designator R173)
R13 "CRCW06037K50FKEA" 0603 6110,2115 r270 top (schematic designator R158)
R14 "CRCW06037K50FKEA" 0603 6780,2115 r270 top (schematic designator R169)
R15 "" 0603 5670,2110 r180 top (schematic designator R142)
R16 "" 0603 6360,2110 r180 top (schematic designator R155)
R17 "" 0603 7030,2110 r180 top (schematic designator R167)
R18 "" 0603 5205,2050 r270 top (schematic designator R6)
R19 "CRCW040222R0JNED" 0402 4975,2050 r90 top (schematic designator R204)
R20 "CRCW040222R0JNED" 0402 5100,2050 r90 top (schematic designator R202)
R21 "" 0603 5400,2000 r270 top (schematic designator R4)
R22 "CRCW06030000Z0EA" 0603 295,1955 r270 top (schematic designator R109)
R23 "" 0603 5585,1965 r180 top (schematic designator R2)
R24 "CRCW06037K50FKEA" 0603 7115,1835 r90 top (schematic designator R159)
R25 "RC0603FR-07270KL" 0603 7215.31,1865 r0 top (schematic designator R161)
R26 "" 0603 7360.31,1865 r180 top (schematic designator R156)
R27 "CRCW0603100KFKEA" 0603 7215.31,1795 r0 top (schematic designator R163)
R28 "" 0603 7360.31,1725 r180 top (schematic designator R157)
R29 "CRCW06034K87FKEA" 0603 805,1660 r270 top (schematic designator R103)
R30 "CRCW0603300RJNEA" 0603 875,1660 r270 top (schematic designator R102)
R31 "RC0603FR-07270KL" 0603 6546,1500 r0 top (schematic designator R145)
R32 "" 0603 6001,1500 r180 top (schematic designator R149)
R33 "" 0603 6691,1500 r180 top (schematic designator R139)
R34 "" 0603 7361,1500 r180 top (schematic designator R164)
R35 "RC0603FR-07270KL" 0603 5855.13,1498.7 r0 top (schematic designator R152)
R36 "RC0603FR-07270KL" 0603 7216,1498.54 r0 top (schematic designator R170)
R37 "CRCW06037K50FKEA" 0603 5751,1465 r90 top (schematic designator R151)
R38 "CRCW06037K50FKEA" 0603 6441,1465 r90 top (schematic designator R143)
R39 "CRCW06037K50FKEA" 0603 7111,1465 r90 top (schematic designator R168)
R40 "CRCW0603100KFKEA" 0603 7216,1430 r0 top (schematic designator R172)
R41 "CRCW0603100KFKEA" 0603 6546,1430 r0 top (schematic designator R147)
R42 "CRCW0603100KFKEA" 0603 5855.13,1428.7 r0 top (schematic designator R153)
R43 "CRCW06030000Z0EA" 0603 1555,1410 r0 top (schematic designator R11)
R44 "CRCW040222R0JNED" 0402 3206.81,1380 r270 top (schematic designator R33)
R45 "CRCW040222R0JNED" 0402 3261.81,1380 r270 top (schematic designator R34)
R46 "CRCW040222R0JNED" 0402 3316.81,1380 r270 top (schematic designator R38)
R47 "CRCW040222R0JNED" 0402 3371.81,1380 r270 top (schematic designator R39)
R48 "CRCW040222R0JNED" 0402 3426.81,1380 r270 top (schematic designator R40)
R49 "CRCW040222R0JNED" 0402 3481.81,1380 r270 top (schematic designator R44)
R50 "CRCW040222R0JNED" 0402 3536.81,1380 r270 top (schematic designator R45)
R51 "CRCW040222R0JNED" 0402 3591.81,1380 r270 top (schematic designator R47)
R52 "CRCW040222R0JNED" 0402 3646.81,1380 r270 top (schematic designator R48)
R53 "CRCW040222R0JNED" 0402 3701.81,1380 r270 top (schematic designator R50)
R54 "CRCW040222R0JNED" 0402 3756.81,1380 r270 top (schematic designator R51)
R55 "CRCW040222R0JNED" 0402 3811.81,1380 r270 top (schematic designator R52)
R56 "CRCW040222R0JNED" 0402 3866.81,1380 r270 top
R57 "CRCW040222R0JNED" 0402 3921.81,1380 r270 top (schematic designator R58)
R58 "CRCW040222R0JNED" 0402 3976.81,1380 r270 top (schematic designator R59)
R59 "CRCW040222R0JNED" 0402 4031.81,1380 r270 top (schematic designator R60)
R60 "CRCW040222R0JNED" 0402 4086.81,1380 r270 top (schematic designator R61)
R61 "CRCW040222R0JNED" 0402 4141.81,1380 r270 top (schematic designator R65)
R62 "CRCW040222R0JNED" 0402 4196.81,1380 r270 top (schematic designator R66)
R63 "CRCW040222R0JNED" 0402 4251.81,1380 r270 top (schematic designator R67)
R64 "CRCW040222R0JNED" 0402 4306.81,1380 r270 top (schematic designator R69)
R65 "CRCW040222R0JNED" 0402 4361.81,1380 r270 top (schematic designator R70)
R66 "CRCW040222R0JNED" 0402 4416.81,1380 r270 top (schematic designator R72)
R67 "CRCW040222R0JNED" 0402 4471.81,1380 r270 top (schematic designator R73)
R68 "" 0603 935,1395 r0 top (schematic designator R8)
R69 "" 0603 6001,1360 r180 top (schematic designator R150)
R70 "" 0603 6691,1360 r180 top (schematic designator R140)
R71 "" 0603 7361,1360 r180 top (schematic designator R165)
R72 "CRCW060310K0FKEA" 0603 1555,1340 r0 top (schematic designator R10)
R73 "" 0603 935,1325 r0 top (schematic designator R9)
R74 "" 0603 935,1240 r0 top (schematic designator R12)
R75 "CRCW0603100RJNEA" 0603 2655,1190 r270 top (schematic designator R53)
R76 "CRCW0603100RJNEA" 0603 2730,1190 r90 top (schematic designator R35)
R77 "" 0603 935,1170 r0 top (schematic designator R13)
R78 "CRCW06034K87FKEA" 0603 3315,1170 r180 top (schematic designator R32)
R79 "CRCW06030000Z0EA" 0603 2545,1155 r0 top (schematic designator R41)
R80 "CRCW060310K0FKEA" 0603 1555,1105 r0 top (schematic designator R16)
R81 "CRCW0603100RJNEA" 0603 2655,1060 r270 top (schematic designator R54)
R82 "CRCW0603100RJNEA" 0603 2730,1060 r90 top (schematic designator R36)
R83 "" 0603 935,1090 r0 top (schematic designator R14)
R84 "CRCW060310K0FKEA" 0603 1555,1040 r0 top (schematic designator R15)
R85 "CRCW06030000Z0EA" 0603 2545,1030 r0 top (schematic designator R46)
R86 "RC0603FR-074K7L" 0603 2080,1030 r180 top (schematic designator R42)
R87 "" 0603 935,1020 r0 top (schematic designator R17)
R88 "RC0603FR-074K7L" 0603 2080,965 r180 top (schematic designator R43)
R89 "CRCW0603100RJNEA" 0603 2655,930 r270 top (schematic designator R55)
R90 "CRCW0603100RJNEA" 0603 2730,930 r90 top (schematic designator R37)
R91 "" 0603 935,935 r0 top (schematic designator R18)
R92 "CRCW06030000Z0EA" 0603 2545,900 r0 top (schematic designator R49)
R93 "CRCW04020000Z0ED" 0402 2020,905 r0 top (schematic designator R195)
R94 "CRCW040222R0JNED" 0402 4895,905 r180 top (schematic designator R85)
R95 "CRCW04020000Z0ED" 0402 2110,870 r90 top (schematic designator R78)
R96 "" 0603 935,865 r0 top (schematic designator R19)
R97 "CRCW04020000Z0ED" 0402 2020,855 r0 top (schematic designator R83)
R98 "CRCW12061K50JNEA" 1206 7240,840 r180 top (schematic designator R120)
R99 "CRCW040222R0JNED" 0402 4895,850 r180 top (schematic designator R86)
R100 "CRCW0603100RJNEA" 0603 2655,800 r270 top (schematic designator R62)
R101 "CRCW0603100RJNEA" 0603 2730,800 r90 top (schematic designator R79)
R102 "CRCW06030000Z0EA" 0603 2545,830 r0 top (schematic designator R68)
R103 "CRCW060310K0JNEA" 0603 4640,785 r270 top (schematic designator R213)
R104 "CRCW04020000Z0ED" 0402 2020,805 r0 top (schematic designator R194)
R105 "CRCW040222R0JNED" 0402 4895,795 r180 top (schematic designator R88)
R106 "CRCW040222R0JNED" 0402 4895,740 r180 top (schematic designator R89)
R107 "" 0603 935,728.54 r0 top (schematic designator R20)
R108 "CRCW06030000Z0EA" 0603 1555,720 r0 top (schematic designator R23)
R109 "CRCW06030000Z0EA" 0603 2545,705 r0 top (schematic designator R71)
R110 "CRCW0603100RJNEA" 0603 2655,670 r270 top (schematic designator R63)
R111 "CRCW0603100RJNEA" 0603 2730,670 r90 top (schematic designator R80)
R112 "CRCW040222R0JNED" 0402 4895,685 r180 top (schematic designator R90)
R113 "CRCW0603100RJNEA" 0603 1915,635 r90 top (schematic designator R84)
R114 "CRCW0603100RJNEA" 0603 1850,635 r270 top (schematic designator R82)
R115 "CRCW0603100RJNEA" 0603 2050,635 r270 top (schematic designator R76)
R116 "CRCW04020000Z0ED" 0402 2120,640 r90 top (schematic designator R57)
R117 "" 0603 935,658.54 r0 top (schematic designator R21)
R118 "CRCW060310K0FKEA" 0603 1555,655 r0 top (schematic designator R22)
R119 "CRCW040222R0JNED" 0402 4380,655 r180 top (schematic designator R132)
R120 "CRCW040222R0JNED" 0402 4895,630 r180 top (schematic designator R91)
R121 "CRCW060310K0JNEA" 0603 4735,590 r90 top (schematic designator R214)
R122 "RC0603FR-07150KL" 0603 6150,585 r180 top (schematic designator R176)
R123 "" 0603 935,573.54 r0 top (schematic designator R24)
R124 "CRCW0603100RJNEA" 0603 2655,540 r270 top (schematic designator R64)
R125 "CRCW0603100RJNEA" 0603 2730,540 r90 top (schematic designator R81)
R126 "CRCW06030000Z0EA" 0603 2545,570 r0 top (schematic designator R74)
R127 "CRCW06034K87FKEA" 0603 4830,505 r270 top (schematic designator R92)
R128 "CRCW0603100KFKEA" 0603 4900,505 r270 top (schematic designator R94)
R129 "CRCW0603100RJNEA" 0603 5005,535 r180 top (schematic designator R95)
R130 "CRCW06030000Z0EA" 0603 1980,500 r90 top (schematic designator R77)
R131 "CRCW12066R80JNEA" 1206 7396,442 r90 top (schematic designator R125)
R132 "" 0603 935,503.54 r0 top (schematic designator R25)
R133 "CRCW040222R0JNED" 0402 4350,450 r90 top (schematic designator R108)
R134 "CRCW0603100RJNEA" 0603 5005,470 r0 top (schematic designator R104)
R135 "CRCW060349R9FKEA" 0603 6335,440 r180 top (schematic designator R123)
R136 "CRCW06034K87FKEA" 0603 4685,420 r0 top (schematic designator R106)
R137 "CRCW060310K0FKEA" 0603 1555,415 r0 top (schematic designator R28)
R138 "" 0603 935,413.54 r0 top (schematic designator R26)
R139 "CRCW06030000Z0EA" 0603 5470,365 r0 top (schematic designator R128)
R140 "CRCW06030000Z0EA" 0603 7023,364 r180 top (schematic designator R205)
R141 "CRCW040222R0JNED" 0402 4790,330 r270 top (schematic designator R97)
R142 "CRCW060310K0FKEA" 0603 1555,350 r0 top (schematic designator R27)
R143 "" 0603 935,343.54 r0 top (schematic designator R29)
R144 "CRCW06034K87FKEA" 0603 3405,305 r90 top (schematic designator R116)
R145 "" 0603 935,258.54 r0 top (schematic designator R30)
R146 "CRCW040222R0JNED" 0402 3775,265 r0 top (schematic designator R112)
R147 "CRCW040222R0JNED" 0402 4225,260 r180 top (schematic designator R107)
R148 "CRCW06034K87FKEA" 0603 3515,210 r270 top (schematic designator R111)
R149 "RC0603FR-071K47L" 0603 7140,205 r90 top (schematic designator R189)
R150 "CRCW06030000Z0EA" 0603 7290,205 r270 top (schematic designator R137)
R151 "CRCW0603137KFKEA" 0603 7365,205 r270 top (schematic designator R129)
R152 "CRCW06034K87FKEA" 0603 4685,220.32 r0 top (schematic designator R110)
R153 "" 0603 935,188.54 r0 top (schematic designator R31)
R154 "CRCW040222R0JNED" 0402 5075,195 r0 top (schematic designator R101)
R155 "CRCW040222R0JNED" 0402 5075,145 r180 top (schematic designator R105)
R156 "CRCW060310K0JNEA" 0603 5010,2255 r90 bottom (schematic designator R209)
R157 "CRCW060310K0JNEA" 0603 5425,2211.62 r90 bottom (schematic designator R208)
R158 "CRCW06030000Z0EA" 0603 660,2020 r90 bottom (schematic designator R96)
R159 "CRCW06030000Z0EA" 0603 3225,1865 r180 bottom (schematic designator R131)
R160 "" 0603 5450,1825 r180 bottom (schematic designator R3)
R161 "" 0603 5315,1825 r180 bottom (schematic designator R5)
R162 "" 0603 5185,1825 r180 bottom (schematic designator R7)
R163 "" 0603 5045,1775 r180 bottom (schematic designator R1)
R164 "CRCW040222R0JNED" 0402 3320,1735 r90 bottom (schematic designator R197)
R165 "CRCW040222R0JNED" 0402 3260,1735 r90 bottom (schematic designator R135)
R166 "CRCW06034K87FKEA" 0603 5545,1245 r0 bottom (schematic designator R98)
R167 "4.7K" R-ACAS_0612 4355,1200 r270 bottom (schematic designator R114)
R168 "CRCW0603300RJNEA" 0603 6296.5,1215 r180 bottom (schematic designator R180)
R169 "RC0603FR-07620RL" 0603 5765,1185 r180 bottom (schematic designator R181)
R170 "CRCW060317K4FKEA" 0603 5960,1105 r270 bottom (schematic designator R188)
R171 "4.7K" R-ACAS_0612 4755,1070 r270 bottom (schematic designator R87)
R172 "RC0603JR-070RL" 0603 6215,1040 r90 bottom (schematic designator R184)
R173 "CRCW060315K0JNEA" 0603 5475,1010 r0 bottom (schematic designator R193)
R174 "CRCW040222R0JNED" 0402 4596.38,970 r180 bottom (schematic designator R134)
R175 "CRCW040222R0JNED" 0402 3198.62,950 r0 bottom (schematic designator R201)
R176 "CRCW060347K5FKEA" 0603 5475,940 r180 bottom (schematic designator R192)
R177 "CRCW060310K2FKEA" 0603 6185,940 r0 bottom (schematic designator R185)
R178 "CRCW06033K24FKEA" 0603 6045,939.49 r0 bottom (schematic designator R186)
R179 "CRCW040222R0JNED" 0402 3205,890 r0 bottom (schematic designator R200)
R180 "RC0603FR-0742K2L" 0603 5575,731.5 r270 bottom (schematic designator R191)
R181 "RT0603BRD0758K3L" 0603 5473.5,695 r180 bottom (schematic designator R190)
R182 "CRCW12060000Z0EA" 1206 6010,530 r90 bottom (schematic designator R118)
R183 "CRCW12060000Z0EA" 1206 5900,530 r270 bottom (schematic designator R138)
R184 "CRCW060348K7FKEA" 0603 6150,585 r0 bottom (schematic designator R183)
R185 "CRCW040222R0JNED" 0402 4390,505 r180 bottom (schematic designator R133)
R186 "CRCW06030000Z0EA" 0603 6989,435 r180 bottom (schematic designator R124)
R187 "CRCW06034K87FKEA" 0603 4470,370 r90 bottom (schematic designator R100)
R188 "CRCW06034K87FKEA" 0603 4400,370 r90 bottom (schematic designator R99)
R189 "CRCW040222R0JNED" 0402 4335,375 r90 bottom (schematic designator R199)
R190 "CRCW060314K0FKEA" 0603 6190,350 r90 bottom (schematic designator R136)
R191 "CRCW0603499RFKEA" 0603 6455,335 r90 bottom (schematic designator R122)
R192 "CRCW06030000Z0EA" 0603 4170,355 r0 bottom (schematic designator R115)
R193 "CRCW06034K99FKEA" 0603 6335,330 r0 bottom (schematic designator R126)
R194 "RC0603JR-0710KL" 0603 3190,280 r90 bottom (schematic designator R212)
R195 "CRCW0603100KFKEA" 0603 5140,285 r0 bottom (schematic designator R93)
R196 "RT0603DRE07301RL" 0603 4965,285 r0 bottom (schematic designator R117)
R197 "RC0603JR-070RL" 0603 5470,280 r180 bottom (schematic designator R215)
R198 "CRCW06031K00FKEA" 0603 6335,260 r180 bottom (schematic designator R127)
R199 "RC0603FR-07220RL" 0603 6460,145 r270 bottom (schematic designator R130)
R200 "CRCW060310K0FKEA" 0603 6395,145 r270 bottom (schematic designator R196)
R201 "RC0603FR-074K7L" 0603 3590,165 r0 bottom (schematic designator R210)
R202 "CRCW06034K87FKEA" 0603 3825,140 r0 bottom (schematic designator R113)
R203 "RC0603FR-074K7L" 0603 2965.87,131.42 r180 bottom (schematic designator R211)
R204 "CRCW06030000Z0EA" 0603 6176,118 r180 bottom (schematic designator R121)
R205 "RC0603JR-070RL" 0603 5515,105 r180 bottom (schematic designator R207)
R206 "RG1608P-911-B-T5" 0603 5715,80 r180 bottom (schematic designator R182)
R207 "RC0603FR-074K7L" 0603 2295,800 r180 bottom
R208 "RC0603FR-074K7L" 0603 2295,730 r180 bottom
S1 "4-1437565-1" SW_FSM4JSMA 5501.42,1354.13 r180 top (schematic designator S2)
S2 "218-4LPST" SW_218-4LPST 4755,1070 r0 top (schematic designator S1)
S3 "4-1437565-1" SW_FSM4JSMA 3145,220 r90 top
T1 "" XFARMER 6675,775 r0 top
TP1 "" TP-040_RND 1230,1545 r90 top (schematic designator TP3)
TP2 "" TP-040_RND 640,1505 r90 top
TP3 "TP-SMALL" TP-SMALL 5705,1285 r90 top (schematic designator TP5)
TP4 "TP-SMALL" TP-SMALL 5890,1145 r90 top (schematic designator TP8)
TP5 "TP-SMALL" TP-SMALL 7450,1125 r90 top (schematic designator TP10)
TP6 "TP-SMALL" TP-SMALL 6385,1115 r90 top (schematic designator TP11)
TP7 "TP-SMALL" TP-SMALL 6215,825 r90 top (schematic designator TP12)
TP8 "TP-SMALL" TP-SMALL 6215,690 r0 top (schematic designator TP1)
TP9 "TP-SMALL" TP-SMALL 5611,177 r90 top (schematic designator TP6)
TP10 "TP-SMALL" TP-SMALL 5395,105 r90 top (schematic designator TP4)
U1 "OPA211AID" SO8 5900,2145 r0 top (schematic designator U19)
U2 "OPA211AID" SO8 6590,2145 r0 top (schematic designator U26)
U3 "OPA211AID" SO8 7260,2145 r0 top (schematic designator U31)
U4 "LMV7219M5X" MF05A_N 6885,2075 r270 top (schematic designator U29)
U5 "LMV7219M5X" MF05A_N 5525,2070 r270 top (schematic designator U17)
U6 "LMV7219M5X" MF05A_N 6215,2070 r270 top (schematic designator U24)
U7 "CP2102" QFN28[RHD] 835,1865 r270 top (schematic designator U8)
U8 "OPA211AID" SO8 7590,1760 r0 top (schematic designator U27)
U9 "ZEN056V130A24LS" "POLYZEN 4 x 4 SMD" 360,1740 r0 top
U10 "REF3012AIDBZ" SOT-23#2 6775,1740 r180 top (schematic designator U22)
U11 "LMV7219M5X" MF05A_N 7215.31,1690 r270 top (schematic designator U25)
U12 "" SOT-23#2 1395,1665 r270 top (schematic designator U20)
U13 "OPA211AID" SO8 6231,1390 r0 top (schematic designator U23)
U14 "OPA211AID" SO8 6921,1390 r0 top (schematic designator U18)
U15 "OPA211AID" SO8 7591,1390 r0 top (schematic designator U30)
U16 "DAC8564IAPW" PW0016A_N 1265,1285 r0 top (schematic designator U1)
U17 "LMV7219M5X" MF05A_N 5856,1325 r270 top (schematic designator U21)
U18 "LMV7219M5X" MF05A_N 6546,1325 r270 top (schematic designator U16)
U19 "LMV7219M5X" MF05A_N 7216,1325 r270 top (schematic designator U28)
U20 "XC6SLX9-2TQG144I" TQG144_N 3834.65,754.84 r0 top (schematic designator U5)
U21 "DAC8564IAPW" PW0016A_N 1265,980 r0 top (schematic designator U2)
U22 "CDCE906PW" PW0020A_L 2320,865 r0 top (schematic designator U6)
U23 "TPS54232D" D0008A_N 6070,845 r90 top (schematic designator U13)
U24 "LP38798SD-ADJ/NOPB" DNT0012B 5465,775 r90 top (schematic designator U14)
U25 "DAC8564IAPW" PW0016A_N 1265,618.54 r0 top (schematic designator U3)
U26 "TPS55340RTE" RTE0016C 7201.93,394.53 r0 top (schematic designator U15)
U27 "N25Q128A13BSE40F" SO8W 4870,404.68 r0 top (schematic designator U7)
U28 "DAC8564IAPW" PW0016A_N 1265,303.54 r0 top (schematic designator U4)
U29 "CDCE913PW" PW0014A_N 4460,280.32 r180 top (schematic designator U10)
U30 "TCMT1107" SOP-4 6680,230 r0 top (schematic designator U36)
U31 "TLV707_SERIES" UDFN-4P-1X1_MM 5507.58,189.75 r0 top (schematic designator U37)
U32 "TL431AIDBZ" SOT-23#2 6377.5,147.5 r270 top (schematic designator U35)
U33 "DS1088LU-100+" DGK8 3880,140 r0 top (schematic designator U11)
U34 "23LC512-I/SN" SO8 5230,2210 r180 bottom (schematic designator U32)
U35 "23LC512-I/SN" SO8 4665,770 r270 bottom (schematic designator U34)
U36 "TPS79912DDCT" DDC0005A_N 3780,690 r180 bottom (schematic designator U12)
U37 "CAT24M01WI-GT3" SO8 2965,329 r270 bottom (schematic designator U33)
Y1 "7B-27.000MEEQ-T" XTAL_TXC-7B 1870,855 r180 top (schematic designator Y2)
Y2 "7B-27.000MEEQ-T" XTAL_TXC-7B 4485,107.5 r270 top (schematic designator Y1)
ZZ1 "" AssemblyNoteLabel 242.37,3033.77 r0 top
ZZ2 "" AssemblyNote 242.37,2924.89 r0 top
ZZ3 "" AssemblyNote 242.37,2836.33 r0 top
ZZ4 "" AssemblyNote 242.37,2747.77 r0 top

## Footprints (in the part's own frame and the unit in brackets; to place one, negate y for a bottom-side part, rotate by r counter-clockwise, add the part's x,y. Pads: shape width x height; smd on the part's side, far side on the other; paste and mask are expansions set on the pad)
142-0711-201 [mil] "Emerson Connectivity recommended land pattern"
  round 68 smd: 1(0,0)
  rect 63x63 smd: 2(-93.5,93.5) 2(-93.5,-93.5) 2(93.5,93.5) 2(93.5,-93.5)
  Top Layer region: -47.5,64.83 -57.02,57.02 -67.05,44.8 -74.5,30.86 -79.09,15.73 -80.64,0 -79.09,-15.73 -74.5,-30.86 -67.05,-44.8 -57.02,-57.02 -47.5,-64.83 -47.5,-140 -140.5,-140 -140.5,140 -47.5,140
  Top Layer region: 140.5,-140 47.5,-140 47.5,-64.83 57.02,-57.02 67.05,-44.8 74.5,-30.86 79.09,-15.73 80.64,0 79.09,15.73 74.5,30.86 67.05,44.8 57.02,57.02 47.5,64.83 47.5,140 140.5,140
  body extent -125,-125 125,125, height 339
0402 [mm] "0402 from SM-752 data"
  rect 0.8x0.6 smd: 1(-0.6,0) 2(0.6,0)
  silkscreen extent -1.22,-0.52 1.22,0.52, body extent -0.55,-0.3 0.55,0.3, height 0.6
403D [mil]
  rect 100x80 smd: 1(-75,0) 2(75,0)
  silkscreen extent -206,-30 -171,16
0603 [mm] "0603 from SM-752 data"
  rect 1x0.95 smd: 1(-0.8,0) 2(0.8,0)
  silkscreen extent -1.52,-0.69 1.52,0.69, body extent -0.87,-0.47 0.87,0.47, height 0.85
0805_HV [mil] "0805 with 30mil clearance between pads"
  rect 50x63 smd: 1(-40,0) 2(40,0)
  silkscreen extent -74,-40 74,40, body extent -43,-29 43,29, height 43
1206 [mm] "1206 from SM-752 data"
  rect 1.3x1.85 smd: 1(-1.45,0) 2(1.45,0)
  silkscreen extent -2.4,-1.21 2.4,1.21, body extent -1.7,-0.9 1.7,0.9, height 1.35
1210 [mm] "1210 from SM-752 data"
  rect 1.3x2.7 smd: 1(-1.45,0) 2(1.45,0)
  silkscreen extent -2.32,-1.57 2.32,1.57, body extent -1.7,-1.35 1.7,1.35, height 1.35
AssemblyNote [mil] "Assembly Note"
AssemblyNoteLabel [mil] "Assembly Note for PCB Labels"
CONN_0878311420 [mm] "Molex Inc 14POS 2MM VERT"
  rect 1.5x1.5 hole 0.914: 1(-6,-1)
  round 1.5 hole 0.914: 2(-6,1) 3(-4,-1) 4(-4,1) 5(-2,-1) 6(-2,1) 7(0,-1) 8(0,1) 9(2,-1) 10(2,1) 11(4,-1) 12(4,1) 13(6,-1) 14(6,1)
  silkscreen extent -9,-3.5 9,3.5
CONN_613040243121 [mil]
  rect 60x60 hole 38: 1(-950,50)
  round 60 hole 38: 2(-950,-50) 3(-850,50) 4(-850,-50) 5(-750,50) 6(-750,-50) 7(-650,50) 8(-650,-50) 9(-550,50) 10(-550,-50) 11(-450,50) 12(-450,-50) 13(-350,50) 14(-350,-50) 15(-250,50) 16(-250,-50) 17(-150,50) 18(-150,-50) 19(-50,50) 20(-50,-50) 21(50,50) 22(50,-50) 23(150,50) 24(150,-50) 25(250,50) 26(250,-50) 27(350,50) 28(350,-50) 29(450,50) 30(450,-50) 31(550,50) 32(550,-50) 33(650,50) 34(650,-50) 35(750,50) 36(750,-50) 37(850,50) 38(850,-50) 39(950,50) 40(950,-50)
  silkscreen extent -1036,-96 1036,385
D0008A_N [mm] "SOIC, 8-Leads, Body 4.9x3.9mm, Pitch 1.27mm, IPC Medium Density"
  oval 2.2x0.6 smd: 1(-2.4,1.905) 2(-2.4,0.635) 3(-2.4,-0.635) 4(-2.4,-1.905) 5(2.4,-1.905) 6(2.4,-0.635) 7(2.4,0.635) 8(2.4,1.905)
  silkscreen extent -1.88,-2.5 0.9,2.89, body extent -2,-2.5 2,2.5, height 1.75
DDC0005A_N [mil]
  rect 62x22 smd: 1(-46,37.4) 2(-46,0) 3(-46,-37.4) 4(46,-37.4) 5(46,37.4)
  silkscreen extent -35,-60 35,60, body extent -60,-60 60,60, height 43
DGK8 [mil]
  rect 50x15 smd mask+2.5: 1(-90.2,39) 2(-90.2,13.4) 3(-90.2,-12.2) 4(-90.2,-37.8) 5(93.4,-37.8) 7(93.4,13.4) 8(93.4,39)
  rect 50x15 smd paste+0 mask+2.5: 6(93.4,-12.2)
  silkscreen extent -158,59 -134,84
DNT0012B [mm] "SON, 12-Leads, Body 4x4mm, Pitch 0.5mm"
  rect 0.6x0.25 smd mask+0.064: 1(-1.9,1.25) 2(-1.9,0.75) 3(-1.9,0.25) 4(-1.9,-0.25) 5(-1.9,-0.75) 6(-1.9,-1.25) 7(1.9,-1.25) 8(1.9,-0.75) 9(1.9,-0.25) 10(1.9,0.25) 11(1.9,0.75) 12(1.9,1.25)
  rect 2.6x3 smd paste-1.3 mask+0.064: 13(0,0)
  silkscreen extent -2.2,-2.2 2.2,2.2, body extent -2.05,-2.05 2.05,2.05, height 0.81
FB0603 [mm]
  rect 0.95x1 smd: 1(-0.75,0) 2(0.75,0)
  silkscreen extent -0.8,-0.7 0.8,0.7
Fiducial10-20 [mm]
  round 1 smd mask+0.5: 1(0,0)
  Top Layer keep-out circle w1.178: c0,0 r0.5
HDR100_1X2 [mil]
  rect 60x60 hole 38: 1(0,0)
  round 60 hole 38: 2(100,0)
  silkscreen extent -50,-50 150,50
HDR100_1X10 [mil]
  rect 60x60 hole 38: 1(0,0) 2(100,0) 3(200,0) 4(300,0) 5(400,0) 6(500,0) 7(600,0) 8(700,0) 9(800,0) 10(900,0)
